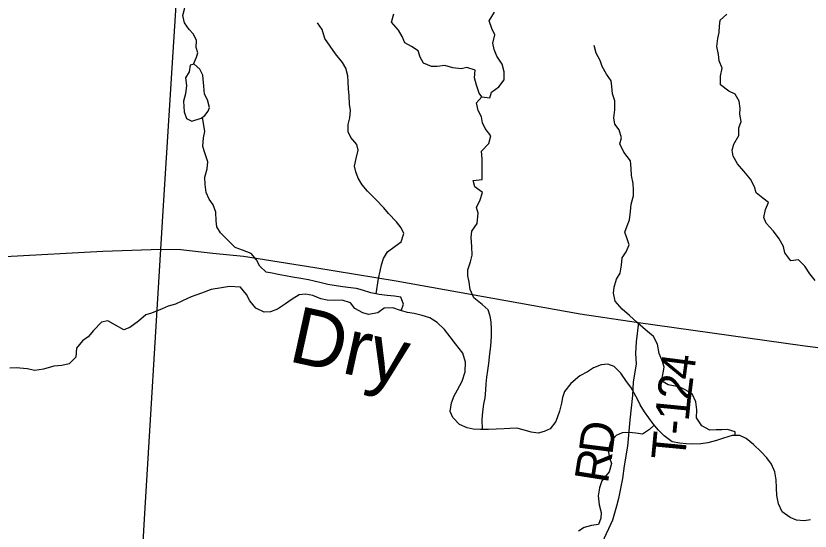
# Model space of a CAD drawing. Extents: x 1759416 to 2214760, y 252598 to 1116833.
# Drawn here: x 1937388 to 1944422, y 854018 to 858579 of the extents above; entities that cross this region are included whole.
import ezdxf

# ---------------------------------------------------------------- set-up
doc = ezdxf.new("R2010")
doc.units = 0
for name, color, linetype in [('GM_X_Minor_Lake', 7, 'Continuous'), ('GM_X_Minor_River', 7, 'Continuous'), ('GM_X_Minor_River_Text', 7, 'Continuous'), ('GM_X_Township_Road', 7, 'Continuous'), ('GM_X_Township_Road_Text', 7, 'Continuous'), ('GM_X_US_Route', 7, 'Continuous')]:
    doc.layers.add(name, color=color, linetype=linetype)

msp = doc.modelspace()

# ---------------------------------------------------------------- linework, layer by layer
at = {"layer": 'GM_X_Minor_Lake'}
for points in [[(1939028.1, 857674.5), (1939060.5, 857698.2), (1939091, 857735.9), (1939103.4, 857767.8), (1939084.3, 857836.2), (1939059, 857886.7), (1939051.9, 857957), (1939043.2, 858055.3), (1939017.9, 858107.8), (1938966.5, 858152.7), (1938930.3, 858143.1), (1938921.5, 858083.1), (1938888.8, 858029.4), (1938899.9, 857961), (1938888.9, 857889), (1938872, 857825), (1938878.7, 857730.7), (1938897.9, 857670.3), (1938945.7, 857647.6)], [(1938945.7, 857647.6), (1939028.1, 857674.5)]]:
    msp.add_lwpolyline(points, dxfattribs=at)
at = {"layer": 'GM_X_Minor_River'}
for points in [[(1938959.9, 858150.9), (1938987.3, 858214.5), (1938999.8, 858250.5), (1938984.5, 858298.8), (1938987.3, 858360.9), (1938962, 858415.4), (1938922.6, 858458.1), (1938881.3, 858516.8), (1938866.2, 858581.2), (1938881, 858637.1), (1938891.9, 858703.2), (1938902.9, 858779.2), (1938935.4, 858818.9), (1938962.1, 858862.6), (1938962.6, 858910.8)], [(1941514.7, 857861.7), (1941489.1, 857894.1), (1941468.1, 857966.6), (1941448.9, 858029), (1941453.8, 858099.1), (1941382.1, 858122.2), (1941331.9, 858108.8), (1941256, 858119.8), (1941186.2, 858140.8), (1941120, 858131.7), (1941067.9, 858130.4), (1940998.3, 858161.4), (1940969, 858211.9), (1940949.7, 858270.4), (1940890.2, 858307.3), (1940832.6, 858340.1), (1940807.3, 858396.6), (1940776, 858451.2), (1940715, 858524.2), (1940733.9, 858596.2)], [(1941520.6, 854916.2), (1941516.2, 855005.9), (1941523.1, 855074), (1941532, 855142.1), (1941542.8, 855198.1), (1941549.7, 855264.2), (1941552.5, 855322.3), (1941559.3, 855380.3), (1941566.1, 855440.4), (1941576.9, 855502.4), (1941586.1, 855586.5), (1941595, 855654.6), (1941600.2, 855744.8), (1941601, 855802.9), (1941595.9, 855869.2), (1941586.6, 855919.4), (1941571.3, 855975.8), (1941517.9, 856022.7), (1941442.7, 856083.8), (1941411.6, 856156.4), (1941402.5, 856220.7), (1941391.2, 856277), (1941389.9, 856329.2), (1941414.9, 856401.1), (1941427.7, 856459), (1941424.8, 856537.3), (1941419.8, 856617.6), (1941426.6, 856671.6), (1941471.5, 856741.2), (1941480.8, 856833.3), (1941465.5, 856883.7), (1941500.4, 856951.4), (1941519.3, 857015.3), (1941451.9, 857066.4), (1941436.6, 857120.7), (1941516.8, 857129.7), (1941517.6, 857185.8), (1941516.5, 857256), (1941517.3, 857314.2), (1941510.2, 857382.4), (1941575.2, 857447.7), (1941594.1, 857515.7), (1941542.9, 857580.5), (1941519.6, 857631), (1941512.3, 857685.2), (1941483, 857739.8), (1941468, 857810.2), (1941514.7, 857861.7), (1941584.6, 857852.7), (1941599.3, 857904.7), (1941666, 857949.9), (1941712.9, 858013.4), (1941711.8, 858083.6), (1941694.7, 858150), (1941647.7, 858222.9), (1941622.4, 858281.4), (1941611.2, 858335.7), (1941628.2, 858409.7), (1941602.9, 858466.1), (1941579.8, 858534.6), (1941626.9, 858610.2)], [(1944465.2, 856235.7), (1944417.9, 856294.5), (1944374.8, 856363.2), (1944319.5, 856420.1), (1944249.4, 856411), (1944198.3, 856481.9), (1944185, 856536.3), (1944147.9, 856604.9), (1944096.8, 856673.8), (1944033.7, 856744.8), (1944012.4, 856795.3), (1944027.3, 856863.3), (1944054.2, 856927.1), (1944002.6, 856963.9), (1943943.2, 857012.8), (1943927.9, 857065.2), (1943892.8, 857133.8), (1943835.7, 857202.8), (1943778.5, 857267.7), (1943741.4, 857336.4), (1943732.1, 857388.7), (1943746.9, 857442.6), (1943790, 857520.2), (1943790.8, 857586.4), (1943811.6, 857642.3), (1943798.5, 857708.6), (1943801.2, 857758.7), (1943794, 857823), (1943756.8, 857885.7), (1943701.2, 857912.5), (1943627.9, 857967.6), (1943628.9, 858043.8), (1943643.9, 858115.8), (1943614.7, 858180.4), (1943611.5, 858236.6), (1943596.4, 858307), (1943605.4, 858379), (1943616.1, 858431), (1943618.8, 858487.1), (1943623.6, 858541.2), (1943684.3, 858594.6)], [(1940577.2, 856116.8), (1940600.3, 856253.6), (1940613.2, 856319.6), (1940625.9, 856375.6), (1940642.7, 856429.5), (1940679.5, 856491.2), (1940746.2, 856540.4), (1940798.8, 856579.8), (1940823.8, 856651.7), (1940800.5, 856702.1), (1940757.2, 856756.8), (1940688.1, 856828), (1940644.8, 856880.7), (1940575.6, 856951.8), (1940500.6, 857027), (1940453.3, 857081.8), (1940418.1, 857142.4), (1940398.8, 857196.8), (1940387.5, 857247.1), (1940400.4, 857317.2), (1940419.4, 857389.1), (1940406.1, 857439.4), (1940352.9, 857502.3), (1940329.5, 857552.7), (1940330.4, 857616.9), (1940345.2, 857674.9), (1940350.1, 857741), (1940340.8, 857797.3), (1940339.8, 857869.5), (1940334.7, 857933.7), (1940329.5, 857993.9), (1940328.2, 858048.1), (1940309.1, 858116.5), (1940279.8, 858167.1), (1940218.7, 858242.1), (1940169.6, 858310.9), (1940124.5, 858377.7), (1940099.6, 858458.3), (1940058.3, 858517)], [(1943759.1, 854864.2), (1943758.6, 854897.5), (1943690.8, 854918.5), (1943640.7, 854915.2), (1943588.6, 854913.8), (1943532.6, 854912.6), (1943463, 854949.6), (1943413.9, 855020.5), (1943416.9, 855092.6), (1943409.8, 855160.9), (1943376.8, 855231.6), (1943295.3, 855278.8), (1943243.5, 855297.5), (1943163.7, 855312.6), (1943104.1, 855347.5), (1943121.1, 855419.5), (1943129.8, 855469.5), (1943114.4, 855519.9), (1943083.3, 855588.5), (1943068.5, 855672.9), (1943033.4, 855741.5), (1942964.1, 855798.6), (1942890.9, 855865.8), (1942821.7, 855926.9), (1942756.4, 855981.9), (1942695.3, 856052.9), (1942680.2, 856125.3), (1942684.9, 856177.4), (1942705.9, 856249.3), (1942738.7, 856301), (1942751.6, 856371), (1942756.5, 856437.2), (1942793.3, 856490.8), (1942818.1, 856552.6), (1942796.9, 856615.1), (1942781.6, 856665.4), (1942800.3, 856719.3), (1942821.1, 856773.2), (1942832.1, 856847.2), (1942837, 856911.4), (1942856, 856985.3), (1942858.7, 857035.4), (1942853.5, 857095.6), (1942840.4, 857166), (1942837.2, 857226.2), (1942830.1, 857294.5), (1942773.1, 857371.5), (1942736.1, 857446.2), (1942750.8, 857498.1), (1942729.8, 857570.6), (1942692.4, 857621.2), (1942683.1, 857675.5), (1942692.1, 857745.6), (1942691.2, 857825.8), (1942672, 857888.2), (1942666.9, 857952.5), (1942659.5, 858002.7), (1942618.3, 858061.4), (1942581.2, 858130.1), (1942561.9, 858182.5), (1942526.7, 858249.2), (1942507.6, 858317.6)], [(1940801.1, 855968.4), (1940819.4, 856026), (1940796.2, 856088.5), (1940740.3, 856097.3), (1940674.3, 856102.2), (1940604.3, 856111.2), (1940532.5, 856126.2), (1940458.7, 856149.2), (1940402.9, 856164), (1940327, 856175), (1940261, 856183.9), (1940151.2, 856199.5), (1940091.3, 856216.3), (1940029.5, 856229.2), (1939977.6, 856241.9), (1939909.7, 856254.8), (1939837.8, 856265.8), (1939773.9, 856278.7), (1939710, 856289.6), (1939658.1, 856300.3), (1939604.2, 856311.1), (1939546.9, 856364), (1939519.6, 856418.5), (1939472.3, 856475.3), (1939394.6, 856504.4), (1939328.9, 856527.4), (1939200.6, 856659.5), (1939167.2, 856710), (1939159.9, 856764.3), (1939157, 856840.5), (1939135.8, 856905), (1939098.5, 856955.6), (1939073.3, 857016.1), (1939064.2, 857086.4), (1939061.1, 857150.7), (1939082.1, 857224.6), (1939086.9, 857286.7), (1939060, 857367.3), (1939042.7, 857421.7), (1939049.7, 857497.8), (1939060.5, 857553.8), (1939039.2, 857682.6)], [(1943653.7, 854840.8), (1943591.4, 854819.6), (1943517, 854798.5), (1943452.9, 854789.3), (1943378.8, 854788.3), (1943324.8, 854789.1), (1943266.8, 854795.8), (1943200.9, 854806.8), (1943129.5, 854859.9), (1943078.2, 854910.7), (1943030.9, 854967.5), (1942993.6, 855020.1), (1942954.3, 855074.8), (1942917.1, 855135.5), (1942893.8, 855185.9), (1942835.1, 855291), (1942795.8, 855341.7), (1942744.7, 855414.5), (1942687.5, 855475.5), (1942629.7, 855496.3), (1942571.6, 855489.1), (1942503.1, 855461.9), (1942450.7, 855428.5), (1942382.1, 855393.3), (1942301.1, 855324.2), (1942246.2, 855254.8), (1942229.4, 855200.9), (1942218.7, 855148.9), (1942201.7, 855078.9), (1942170.5, 854989.1), (1942119.6, 854923.6), (1942067.2, 854898.2), (1942013, 854884.9), (1941951, 854893.8), (1941881.3, 854914.8), (1941825.4, 854927.5), (1941763.3, 854926.4), (1941713.2, 854923), (1941641.1, 854920), (1941573, 854916.9), (1941501, 854915.9), (1941437, 854920.7), (1941383.1, 854931.5), (1941315.4, 854962.5), (1941258.2, 855023.4), (1941234.9, 855075.9), (1941246, 855153.9), (1941268.8, 855213.8), (1941297.5, 855267.5), (1941338.6, 855345.2), (1941367.8, 855427), (1941368.9, 855513.3), (1941346, 855593.8), (1941281, 855674.9), (1941233.8, 855737.7), (1941182.7, 855802.5), (1941117.5, 855865.6), (1941054, 855906.5), (1940986.2, 855925.5), (1940914.4, 855944.5), (1940854.4, 855953.4), (1940794.6, 855970.2), (1940726.9, 855993.2), (1940648.7, 855990.2), (1940592.1, 855948.9), (1940511.9, 855935.9), (1940460, 855948.6), (1940390.5, 855987.7), (1940351.1, 856038.3), (1940277.4, 856061.4), (1940207.3, 856060.3), (1940143.3, 856063.2), (1940089.4, 856073.9), (1940017.7, 856103), (1939951.9, 856115.9), (1939895.8, 856110.7), (1939833.2, 856071.4), (1939776.6, 856030), (1939703.9, 855982.9), (1939641.5, 855959.7), (1939585.4, 855956.4), (1939513.8, 855991.4), (1939460.7, 856056.3), (1939429.4, 856112.9), (1939376.2, 856175.8), (1939278.2, 856183.1), (1939210, 856172), (1939117.7, 856155.2), (1939031.2, 856124.3), (1938938.7, 856091.4), (1938864.2, 856056.3), (1938799.7, 856027.1), (1938735.4, 856007.9), (1938683.1, 855984.6), (1938588.5, 855945.7), (1938538.2, 855932.4), (1938473.4, 855875.1), (1938396.6, 855820), (1938342.3, 855800.7), (1938270.8, 855839.7), (1938201.2, 855878.8)], [(1938201.2, 855878.8), (1938147, 855867.4), (1938076, 855792.2), (1938027.2, 855738.7), (1937976.7, 855701.3), (1937923.7, 855637.8), (1937918.7, 855557.7), (1937859.8, 855498.3), (1937795.6, 855485.1), (1937723.4, 855478.1), (1937633, 855451.2), (1937556.8, 855440.2), (1937486.9, 855455.2), (1937391, 855464.5), (1937334.9, 855459.2)], [(1943041.1, 854955.2), (1942998.2, 854917.8), (1942937.6, 854874.5), (1942877.7, 854883.3), (1942819.7, 854890.1), (1942757.6, 854886.9), (1942703.2, 854863.6), (1942652.5, 854808.1), (1942633.4, 854728.2), (1942644.5, 854665.8), (1942663.9, 854615.4), (1942640.9, 854541.6), (1942577.8, 854464.2), (1942554.9, 854400.3), (1942545.9, 854330.3), (1942552.9, 854249.9), (1942569.9, 854181.5), (1942569.3, 854131.4), (1942546.5, 854075.6), (1942486.4, 854068.3), (1942420, 854049.2), (1942369.6, 854015.8)], [(1944424.6, 854118.5), (1944368.4, 854107.2), (1944300.4, 854114.1), (1944244.7, 854138.9), (1944175.3, 854188), (1944140.3, 854258.7), (1944127.2, 854333), (1944124.2, 854401.3), (1944121.1, 854471.5), (1944110.1, 854541.8), (1944079, 854610.4), (1944037.7, 854665.2), (1943988.4, 854720), (1943921.2, 854785), (1943855.8, 854838.1), (1943800.2, 854864.9), (1943732.1, 854863.8), (1943653.7, 854840.8)]]:
    msp.add_lwpolyline(points, dxfattribs=at)
at = {"layer": 'GM_X_Township_Road'}
for points in [[(1938671.6, 856514.3), (1938696.1, 856899.2), (1938771.7, 858118.7), (1938867.3, 859597), (1938966.8, 861021.1), (1939064.4, 862489.3), (1939107.9, 863107.2), (1939108.2, 863111.8)], [(1938490, 853677.1), (1938508.4, 853819), (1938533, 854224.6), (1938671.6, 856514.3)], [(1942902.5, 855865.5), (1942881, 855692.9), (1942876.2, 855592.3), (1942880.7, 855495), (1942854, 855339.7), (1942848.9, 855217.7), (1942825.6, 854999), (1942805.2, 854770.1), (1942775.6, 854594.1), (1942760.1, 854484.3), (1942723.2, 854305.1), (1942708.1, 854239.1), (1942672, 854115.4), (1942578.5, 853918.3), (1942555.9, 853795.6), (1942509.7, 853670.3), (1942434.9, 853451.4), (1942406.5, 853376.2), (1942395.4, 853325.1), (1942380.8, 853051.5)]]:
    msp.add_lwpolyline(points, dxfattribs=at)
at = {"layer": 'GM_X_US_Route'}
msp.add_lwpolyline([(1937294.1, 856449.6), (1938156.4, 856494.5), (1938671.6, 856514.3), (1938847.8, 856509.3), (1939132.9, 856478), (1939404.5, 856450.6), (1940033.7, 856351.6), (1940754.2, 856232.3), (1942384.9, 855939.9), (1942902.5, 855865.5), (1944354.9, 855661.8), (1945267.5, 855542)], dxfattribs=at)

# ---------------------------------------------------------------- texts
at = {"layer": 'GM_X_Minor_River_Text'}
msp.add_text('Dry', height=500.03, rotation=347.60627, dxfattribs=at).set_placement((1939790.6, 855524.3))
at = {"layer": 'GM_X_Township_Road_Text'}
for s, rotation, p in [('4', 82.57935, (1943385.4, 855348)), ('2', 83.10927, (1943363.3, 855165.2)), ('1', 84.40177, (1943345.5, 854983.1)), ('D', 82.76471, (1942669.5, 854685.3)), ('-', 84.59, (1943333.9, 854860.7)), ('T', 84.6267, (1943312.9, 854637.3)), ('R', 81.01377, (1942629.6, 854432.2))]:
    msp.add_text(s, height=300, rotation=rotation, dxfattribs=at).set_placement(p)

doc.saveas('drawing.dxf')
